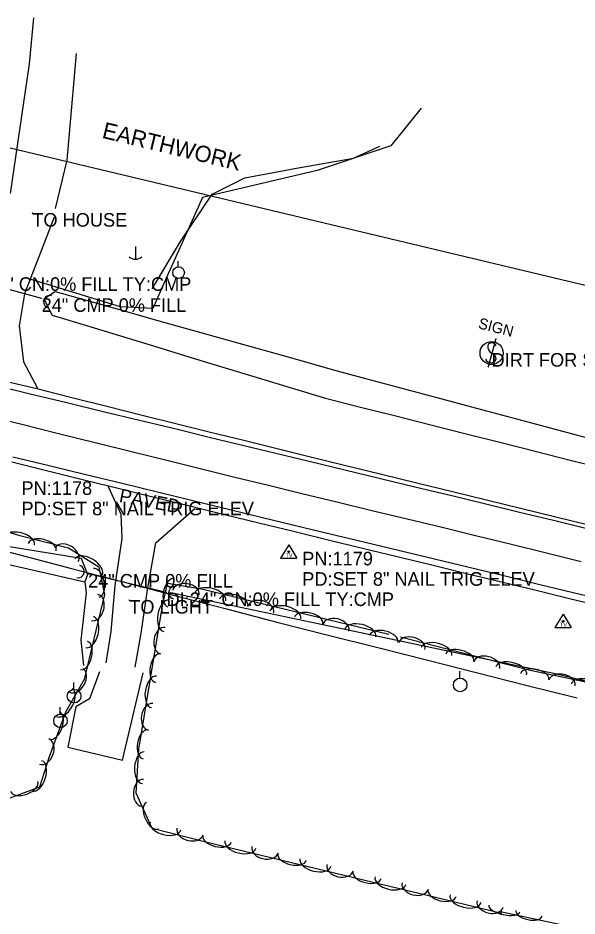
# Model space of a CAD drawing. Extents: x 1441650 to 1491889, y 345904 to 358319.
# Drawn here: x 1458522.3 to 1458728.2, y 351345.2 to 351675.9 of the extents above; entities that cross this region are included whole.
import ezdxf

# ---------------------------------------------------------------- set-up
doc = ezdxf.new("R2010")
doc.units = 0
for name, color, linetype in [('S_CROSS_DRAIN', 7, 'Continuous'), ('S_CROSS_DRAIN_ANNOT', 7, 'Continuous'), ('S_DITCHLINE', 7, 'Continuous'), ('S_DRG_PT_SYM', 7, 'Continuous'), ('S_EDGE_PAVEMENT', 7, 'Continuous'), ('S_GRAVEL_ROAD', 7, 'Continuous'), ('S_MISC_BOUNDARY', 7, 'Continuous'), ('S_MISC_BOUNDARY_ANNOT', 7, 'Continuous'), ('S_MSC_PT_SYM', 7, 'Continuous'), ('S_PARKING', 7, 'Continuous'), ('S_PARKING_ANNOT', 7, 'Continuous'), ('S_PAVEMENT_CROWN', 7, 'Continuous'), ('S_SECONDARY_CTL', 7, 'Continuous'), ('S_SECONDARY_CTL_ANNOT', 7, 'Continuous'), ('S_SHOULDER', 7, 'Continuous'), ('S_SIGN', 7, 'Continuous'), ('S_SIGN_ANNOT', 7, 'Continuous'), ('S_STREAM', 7, 'Continuous'), ('S_SURVEY_TEXT_ANNOT', 7, 'Continuous'), ('S_TREE', 7, 'Continuous'), ('S_UTILITY_POLE', 7, 'Continuous'), ('S_WATER_UTILITIES', 7, 'Continuous')]:
    doc.layers.add(name, color=color, linetype=linetype)

msp = doc.modelspace()

# ---------------------------------------------------------------- linework, layer by layer
at = {"layer": 'S_CROSS_DRAIN'}
for p, q in [((1458502.43, 351580.4), (1458531.05, 351572.66)), ((1458577.05, 351464.33), (1458548.17, 351471.12))]:
    msp.add_line(p, q, dxfattribs=at)
for centre, start, end in [((1458534.06, 351571.39), 74.1339, 254.463), ((1458544.46, 351472.05), 257.4017, 77.7308), ((1458580.1, 351464.22), 76.0714, 256.4006)]:
    msp.add_arc(centre, 2.3, start, end, dxfattribs=at)
at = {"layer": 'S_DITCHLINE'}
for points in [[(1458531.81, 351572.44), (1458536.01, 351575.16), (1458548.76, 351571.58), (1458561.51, 351568), (1458574.26, 351564.41), (1458587.01, 351560.83), (1458599.76, 351557.24), (1458612.51, 351553.66), (1458625.26, 351550.08), (1458638.01, 351546.49), (1458650.86, 351543.05), (1458663.7, 351539.6), (1458676.55, 351536.16), (1458689.39, 351532.71), (1458702.24, 351529.27), (1458715.09, 351525.82), (1458727.93, 351522.38), (1458740.78, 351518.93), (1458764.46, 351513.29), (1458788.14, 351507.66), (1458811.82, 351502.02), (1458835.51, 351496.38)], [(1458531.82, 351572.47), (1458531.81, 351572.44), (1458534.96, 351566.41), (1458547.53, 351562.59), (1458560.1, 351558.78), (1458572.67, 351554.97), (1458585.24, 351551.15), (1458597.81, 351547.34), (1458610.39, 351543.52), (1458622.96, 351539.71), (1458635.53, 351535.9), (1458648.48, 351532.62), (1458661.44, 351529.35), (1458674.4, 351526.07), (1458687.35, 351522.8), (1458700.31, 351519.53), (1458713.27, 351516.25), (1458726.22, 351512.98), (1458739.18, 351509.7)], [(1458512.39, 351482.35), (1458528.99, 351479.68), (1458545.6, 351477.01), (1458548, 351470.96), (1458547, 351468.22), (1458547.4, 351464.15), (1458545.54, 351446.8), (1458546.42, 351437.38)], [(1458510.32, 351476.59), (1458528.66, 351472.41), (1458547, 351468.23)]]:
    msp.add_lwpolyline(points, dxfattribs=at)
at = {"layer": 'S_DRG_PT_SYM'}
for points in [[(1458531.05, 351572.66), (1458531.05, 351572.71), (1458531.05, 351572.66), (1458531, 351572.66), (1458531.05, 351572.66), (1458531.05, 351572.61), (1458531.05, 351572.66), (1458531.1, 351572.66)], [(1458548.17, 351471.12), (1458548.17, 351471.17), (1458548.17, 351471.12), (1458548.12, 351471.12), (1458548.17, 351471.12), (1458548.17, 351471.07), (1458548.17, 351471.12), (1458548.22, 351471.12)], [(1458577.05, 351464.33), (1458577.05, 351464.38), (1458577.05, 351464.33), (1458577, 351464.33), (1458577.05, 351464.33), (1458577.05, 351464.28), (1458577.05, 351464.33), (1458577.1, 351464.33)]]:
    msp.add_lwpolyline(points, dxfattribs=at)
at = {"layer": 'S_EDGE_PAVEMENT'}
for points in [[(1458514.28, 351540.54), (1458526.88, 351537.49), (1458540.3, 351534.25), (1458553.73, 351531.01), (1458567.15, 351527.77), (1458580.58, 351524.53), (1458592.81, 351521.56), (1458605.05, 351518.6), (1458617.28, 351515.64), (1458629.52, 351512.68), (1458642.68, 351509.5), (1458655.84, 351506.32), (1458668.99, 351503.15), (1458682.15, 351499.97), (1458694.61, 351496.95), (1458707.07, 351493.93), (1458719.53, 351490.91), (1458731.98, 351487.89)], [(1458520.44, 351514.32), (1458533.87, 351511.06), (1458547.3, 351507.79), (1458560.73, 351504.53), (1458574.16, 351501.26), (1458586.76, 351498.2), (1458599.36, 351495.13), (1458611.96, 351492.07), (1458624.56, 351489), (1458637.35, 351485.92), (1458650.14, 351482.85), (1458662.93, 351479.77), (1458675.72, 351476.69), (1458688.5, 351473.6), (1458701.27, 351470.51), (1458714.05, 351467.42), (1458726.82, 351464.33), (1458739.73, 351461.21)]]:
    msp.add_lwpolyline(points, dxfattribs=at)
at = {"layer": 'S_GRAVEL_ROAD'}
for points in [[(1458535.7, 351602.49), (1458530.04, 351587.89), (1458524.73, 351574.32), (1458522.76, 351562.46), (1458524.36, 351549.28), (1458529.55, 351539.62)], [(1458555.6, 351503.3), (1458560.22, 351493.14), (1458560.61, 351484.24), (1458557.96, 351466.92), (1458556.49, 351449.97), (1458554.67, 351438.38)], [(1458565.52, 351436.8), (1458567.75, 351449.37), (1458570.01, 351465.31), (1458573.15, 351482.64), (1458587.47, 351495.24), (1458587.55, 351495.23)]]:
    msp.add_lwpolyline(points, dxfattribs=at)
at = {"layer": 'S_MISC_BOUNDARY'}
msp.add_lwpolyline([(1458670.83, 351642.69), (1458659.69, 351628.83), (1458632.47, 351619.67), (1458590.27, 351609.76), (1458576.07, 351578.08), (1458571.97, 351568.89), (1458560.12, 351569.49), (1458527.15, 351579.6)], dxfattribs=at)
at = {"layer": 'S_MSC_PT_SYM'}
for points in [[(1458527.64, 351604.04), (1458527.64, 351604.09), (1458527.64, 351604.04), (1458527.59, 351604.04), (1458527.64, 351604.04), (1458527.64, 351603.99), (1458527.64, 351604.04), (1458527.69, 351604.04)], [(1458698.33, 351557.73), (1458698.33, 351557.78), (1458698.33, 351557.73), (1458698.28, 351557.73), (1458698.33, 351557.73), (1458698.33, 351557.68), (1458698.33, 351557.73), (1458698.38, 351557.73)], [(1458695.54, 351547.46), (1458695.54, 351547.51), (1458695.54, 351547.46), (1458695.49, 351547.46), (1458695.54, 351547.46), (1458695.54, 351547.41), (1458695.54, 351547.46), (1458695.59, 351547.46)], [(1458563.32, 351461.54), (1458563.32, 351461.59), (1458563.32, 351461.54), (1458563.27, 351461.54), (1458563.32, 351461.54), (1458563.32, 351461.49), (1458563.32, 351461.54), (1458563.37, 351461.54)]]:
    msp.add_lwpolyline(points, dxfattribs=at)
at = {"layer": 'S_PARKING'}
for points in [[(1458519.58, 351611.25), (1458526.63, 351658.97), (1458528.14, 351675.9)], [(1458543.81, 351662.77), (1458540.38, 351623.51), (1458536.1, 351605.74)], [(1458552.34, 351435.08), (1458548.67, 351425.12), (1458543.65, 351422.15), (1458540.71, 351407.39), (1458560.8, 351402.55), (1458568.47, 351434.67)]]:
    msp.add_lwpolyline(points, dxfattribs=at)
at = {"layer": 'S_PAVEMENT_CROWN'}
msp.add_lwpolyline([(1458511.34, 351529.24), (1458523.77, 351526.24), (1458537.24, 351522.9), (1458550.71, 351519.55), (1458564.18, 351516.21), (1458577.65, 351512.87), (1458589.95, 351509.84), (1458602.26, 351506.82), (1458614.56, 351503.8), (1458626.87, 351500.78), (1458639.79, 351497.67), (1458652.71, 351494.55), (1458665.63, 351491.44), (1458678.55, 351488.33), (1458691.35, 351485.19), (1458704.14, 351482.05), (1458716.94, 351478.9), (1458729.73, 351475.76)], dxfattribs=at)
at = {"layer": 'S_SECONDARY_CTL'}
for p, q in [((1458622.03, 351481.92), (1458619.02, 351476.96)), ((1458622.03, 351481.92), (1458624.98, 351476.96)), ((1458619.02, 351476.96), (1458624.98, 351476.96)), ((1458723.11, 351456.33), (1458720.1, 351451.38)), ((1458723.11, 351456.33), (1458726.05, 351451.38)), ((1458720.1, 351451.38), (1458726.05, 351451.38))]:
    msp.add_line(p, q, dxfattribs=at)
for centre, radius in [((1458622.03, 351479.3), 0.311), ((1458622.03, 351479.3), 0.183), ((1458622.03, 351479.3), 0.103), ((1458723.11, 351453.72), 0.311), ((1458723.11, 351453.72), 0.183), ((1458723.11, 351453.72), 0.103)]:
    msp.add_circle(centre, radius, dxfattribs=at)
at = {"layer": 'S_SHOULDER'}
for points in [[(1458516.19, 351542.5), (1458529.3, 351539.43), (1458542.21, 351536.17), (1458555.12, 351532.9), (1458568.03, 351529.64), (1458580.94, 351526.38), (1458593.21, 351523.37), (1458605.48, 351520.35), (1458617.75, 351517.34), (1458630.02, 351514.32), (1458643.11, 351511.11), (1458656.2, 351507.89), (1458669.28, 351504.67), (1458682.37, 351501.45), (1458694.87, 351498.41), (1458707.38, 351495.37), (1458719.88, 351492.33), (1458732.38, 351489.28)], [(1458520.14, 351512.4), (1458533.34, 351509.12), (1458546.54, 351505.84), (1458559.75, 351502.56), (1458572.95, 351499.28), (1458585.66, 351496.18), (1458598.37, 351493.08), (1458611.08, 351489.98), (1458623.79, 351486.87), (1458636.53, 351483.76), (1458649.27, 351480.66), (1458662.01, 351477.55), (1458674.75, 351474.44), (1458687.55, 351471.33), (1458700.34, 351468.22), (1458713.13, 351465.11), (1458725.93, 351462), (1458738.93, 351458.88)]]:
    msp.add_lwpolyline(points, dxfattribs=at)
at = {"layer": 'S_SIGN'}
msp.add_line((1458698.33, 351557.73), (1458695.54, 351547.46), dxfattribs=at)
msp.add_circle((1458696.74, 351552.49), 4.24, dxfattribs=at)
for centre, radius, start, end in [((1458696.87, 351554.65), 1.62, 16.5258, 156.8957), ((1458697.91, 351554.74), 2.55, 167.1196, 241.9813), ((1458696.48, 351551.09), 2.17, 204.641, 335.359), ((1458696.04, 351550.21), 2.38, 358.6529, 73.7063)]:
    msp.add_arc(centre, radius, start, end, dxfattribs=at)
at = {"layer": 'S_STREAM'}
for points in [[(1458571.71, 351576.18), (1458582.17, 351593.54), (1458593.85, 351610.96), (1458605.89, 351616.99), (1458624.95, 351620.63), (1458645.84, 351624.26), (1458655.54, 351628.67)], [(1458578.61, 351464.35), (1458632.28, 351453), (1458720.19, 351434.47), (1458817.6, 351411.03), (1458920.11, 351387.75), (1459007.82, 351366.75), (1459084.49, 351347.81), (1459170.91, 351328.16), (1459288.39, 351301.52), (1459381.79, 351277.55), (1459486.81, 351250.35), (1459558.24, 351231.73), (1459664.82, 351202.09)]]:
    msp.add_lwpolyline(points, dxfattribs=at)
at = {"layer": 'S_TREE'}
for points in [[(1458482.5, 351497.64), (1458523.05, 351485.26), (1458540.91, 351480.75), (1458552.18, 351473.8), (1458554.24, 351463.57), (1458550.3, 351447.24), (1458546.7, 351432.31), (1458539.83, 351420.23), (1458533.72, 351403.42), (1458530.21, 351392.58), (1458517.97, 351388.12), (1458470.23, 351399.5), (1458352.75, 351427.72), (1458253.25, 351451.71), (1458168.6, 351472.11), (1458080.78, 351493.28), (1457975, 351518.81)], [(1458504.02, 351483.11), (1458523.05, 351478.13), (1458542.09, 351473.16), (1458561.12, 351468.19), (1458580.15, 351463.21), (1458599.18, 351458.24), (1458618.21, 351453.27), (1458636.54, 351448.63), (1458654.88, 351444), (1458673.22, 351439.37), (1458691.56, 351434.73), (1458709.9, 351430.1), (1458728.23, 351425.46)], [(1458504.02, 351483.11), (1458523.05, 351478.13), (1458542.09, 351473.16), (1458561.12, 351468.19), (1458580.15, 351463.21), (1458599.18, 351458.24), (1458618.21, 351453.27), (1458636.54, 351448.63), (1458654.88, 351444), (1458673.22, 351439.37), (1458691.56, 351434.73), (1458709.9, 351430.1), (1458728.23, 351425.46)], [(1458700.49, 351346.14), (1458591.52, 351372.4), (1458571.7, 351377.34), (1458565.84, 351390.42), (1458566.8, 351406.55), (1458575.51, 351459.45), (1458577.42, 351467.73), (1458589.88, 351465.64), (1458632.47, 351455.37), (1458658.95, 351448.99)], [(1458663.18, 351448.03), (1458711.01, 351435.73), (1458759.57, 351425.5), (1458796.96, 351415.82), (1458856.35, 351399.3), (1458956.09, 351373.48), (1459049.81, 351352.01), (1459148.97, 351326.34), (1459247.8, 351301.46), (1459338.76, 351279.57), (1459440.78, 351257.04), (1459527.02, 351234.71), (1459625.47, 351213.15), (1459671.91, 351201.13), (1459683.42, 351198.15)], [(1459653.76, 351114.56), (1459499.42, 351153.65), (1459384.1, 351181.62), (1459274.65, 351206.88), (1459222.5, 351219.2), (1459116.91, 351246.53), (1459028.16, 351266.78), (1458976.84, 351280.06), (1458875.39, 351301.41), (1458841.5, 351311.25), (1458791.59, 351327.01), (1458699.46, 351346.83)]]:
    msp.add_lwpolyline(points, dxfattribs=at)
for centre, major_axis, ratio, start_param, end_param in [((1458522.76, 351483.14), (-5.62, 1.43), 0.55612, 3.145692, 6.287285), ((1458531.26, 351481), (-5.12, 1.31), 0.546637, 3.145562, 6.287155), ((1458540.31, 351478.32), (-4.2, 2.6), 0.686629, 3.14437, 6.285963), ((1458548.31, 351473.69), (-4.98, 3.07), 0.551139, 3.143285, 6.284878), ((1458551.21, 351467.87), (-1.06, 5.24), 0.540694, 3.141504, 6.283096), ((1458578.8, 351464.29), (-1.21, -5.21), 0.540699, 3.141593, 6.283185), ((1458584.19, 351464.18), (-4.89, 0.82), 0.685311, 3.141593, 6.283185), ((1458550.63, 351458.8), (1.16, 4.82), 0.685315, 3.141574, 6.283167), ((1458593.16, 351462.66), (-5.7, 1.38), 0.55008, 3.141593, 6.283185), ((1458601.78, 351460.59), (-5.2, 1.25), 0.540699, 3.141593, 6.283185), ((1458577.05, 351455.74), (-0.95, -5.79), 0.55008, 3.141593, 6.283185), ((1458611.74, 351457.92), (-4.82, 1.16), 0.685311, 3.141593, 6.283185), ((1458620.8, 351456), (-5.7, 1.38), 0.55008, 3.141593, 6.283185), ((1458629.42, 351453.92), (-5.2, 1.25), 0.540699, 3.141593, 6.283185), ((1458548.72, 351449.73), (1.38, 5.7), 0.550083, 3.141581, 6.283174), ((1458639.37, 351451.26), (-4.82, 1.16), 0.685311, 3.141593, 6.283185), ((1458575.8, 351446.57), (-0.8, -4.89), 0.685311, 3.141593, 6.283185), ((1458648.43, 351449.34), (-5.7, 1.38), 0.55008, 3.141593, 6.283185), ((1458657.05, 351447.26), (-5.2, 1.25), 0.540699, 3.141593, 6.283185), ((1458667.41, 351444.59), (-4.8, 1.23), 0.654284, 3.141593, 6.283185), ((1458546.64, 351441.11), (1.25, 5.2), 0.540697, 3.141593, 6.283185), ((1458676.44, 351442.53), (-5.68, 1.46), 0.525175, 3.141593, 6.283185), ((1458685.03, 351440.32), (-5.18, 1.33), 0.51622, 3.141593, 6.283185), ((1458573.87, 351436.44), (-0.87, -5.28), 0.540699, 3.141593, 6.283185), ((1458694.94, 351437.51), (-4.8, 1.23), 0.654284, 3.141593, 6.283185), ((1458703.97, 351435.44), (-5.68, 1.46), 0.525175, 3.141593, 6.283185), ((1458543.76, 351431.96), (2.45, 4.31), 0.685262, 3.141549, 6.283141), ((1458572.43, 351427.69), (-0.95, -5.79), 0.55008, 3.141593, 6.283185), ((1458712.66, 351433.31), (-5.23, 1.1), 0.51625, 3.140604, 6.282197), ((1458722.69, 351430.94), (-4.85, 1.02), 0.654322, 3.139985, 6.281578), ((1458731.8, 351429.28), (-5.74, 1.21), 0.525207, 3.140574, 6.282166), ((1458539.41, 351423.78), (2.9, 5.1), 0.550041, 3.141566, 6.283159), ((1458571.19, 351418.52), (-0.8, -4.89), 0.685311, 3.141593, 6.283185), ((1458535.79, 351415.33), (1.83, 5.02), 0.540687, 3.141593, 6.283185), ((1458569.26, 351408.39), (-0.87, -5.28), 0.540699, 3.141593, 6.283185), ((1458532.02, 351405.74), (1.69, 4.66), 0.685295, 3.141593, 6.283185), ((1458568.52, 351399.78), (-0.35, -5.86), 0.55008, 3.141593, 6.283185), ((1458529.34, 351396.78), (1.8, 5.58), 0.550071, 3.141593, 6.283185), ((1458524.66, 351392.81), (5.02, 1.83), 0.540463, 3.141593, 6.283185), ((1458568.23, 351390.53), (-0.3, -4.95), 0.685311, 3.141593, 6.283185), ((1458571.89, 351382.12), (2.19, -4.88), 0.540699, 3.141593, 6.283185), ((1458576.66, 351378.29), (5.69, -1.42), 0.55008, 3.141593, 6.283185), ((1458585.71, 351376.3), (4.81, -1.2), 0.685311, 3.141593, 6.283185), ((1458595.64, 351373.59), (5.2, -1.25), 0.540699, 3.141593, 6.283185), ((1458604.26, 351371.51), (5.7, -1.38), 0.55008, 3.141593, 6.283185), ((1458613.32, 351369.6), (4.82, -1.16), 0.685311, 3.141593, 6.283185), ((1458623.27, 351366.93), (5.2, -1.25), 0.540699, 3.141593, 6.283185), ((1458631.89, 351364.85), (5.7, -1.38), 0.55008, 3.141593, 6.283185), ((1458640.95, 351362.94), (4.82, -1.16), 0.685311, 3.141593, 6.283185), ((1458650.91, 351360.27), (5.2, -1.25), 0.540699, 3.141593, 6.283185), ((1458659.53, 351358.19), (5.7, -1.38), 0.55008, 3.141593, 6.283185), ((1458668.59, 351356.27), (4.82, -1.16), 0.685311, 3.141593, 6.283185), ((1458678.54, 351353.61), (5.2, -1.25), 0.540699, 3.141593, 6.283185), ((1458687.17, 351351.53), (5.7, -1.38), 0.55008, 3.141593, 6.283185), ((1458696.23, 351349.61), (4.82, -1.16), 0.685311, 3.141593, 6.283185), ((1458701.42, 351347.93), (5.73, -1.26), 0.387863, 3.154269, 6.295862), ((1458710.5, 351346.17), (4.83, -1.08), 0.483168, 3.159096, 6.300688)]:
    msp.add_ellipse(centre, major_axis=major_axis, ratio=ratio, start_param=start_param, end_param=end_param, dxfattribs=at)
at = {"layer": 'S_UTILITY_POLE'}
for p, q in [((1458565.58, 351591.73), (1458565.58, 351587.01)), ((1458581.39, 351584.24), (1458581.39, 351586.35)), ((1458685.04, 351432.8), (1458685.04, 351435.28)), ((1458542.87, 351428.65), (1458542.87, 351431.13)), ((1458537.84, 351419.57), (1458537.84, 351422.05))]:
    msp.add_line(p, q, dxfattribs=at)
for centre, radius in [((1458581.51, 351582.1), 2.13), ((1458685.18, 351430.28), 2.5), ((1458543.02, 351426.13), 2.5), ((1458537.99, 351417.05), 2.5)]:
    msp.add_circle(centre, radius, dxfattribs=at)
msp.add_arc((1458565.64, 351590.43), 3.41, 226.3972, 313.6028, dxfattribs=at)
at = {"layer": 'S_WATER_UTILITIES'}
msp.add_line((1458511.04, 351630.06), (1458843.16, 351550.73), dxfattribs=at)

# ---------------------------------------------------------------- texts
at = {"layer": 'S_CROSS_DRAIN_ANNOT'}
for s, p in [('DI:24" CN:0% FILL TY:CMP', (1458502.43, 351575.4)), ('24" CMP 0% FILL', (1458531.05, 351567.66)), ('24" CMP 0% FILL', (1458548.17, 351466.12)), ('DI:24" CN:0% FILL TY:CMP', (1458577.05, 351459.33))]:
    msp.add_text(s, height=5, dxfattribs=at).set_placement(p)
at = {"layer": 'S_MISC_BOUNDARY_ANNOT'}
msp.add_text('EARTHWORK', height=6, rotation=346.4469, dxfattribs=at).set_placement((1458553, 351631.8))
at = {"layer": 'S_PARKING_ANNOT'}
msp.add_text('PAVED', height=5, rotation=349.0406, dxfattribs=at).set_placement((1458559.35, 351497.68))
at = {"layer": 'S_SECONDARY_CTL'}
for p in [(1458620.83, 351477.29), (1458721.9, 351451.71)]:
    msp.add_text('TV', height=1.5, rotation=360, dxfattribs=at).set_placement(p)
at = {"layer": 'S_SECONDARY_CTL_ANNOT'}
for s, p in [('PN:1178', (1458523.63, 351500.24)), ('PD:SET 8" NAIL TRIG ELEV', (1458523.63, 351492.74)), ('PN:1179', (1458627.03, 351474.3)), ('PD:SET 8" NAIL TRIG ELEV', (1458627.03, 351466.8))]:
    msp.add_text(s, height=5, dxfattribs=at).set_placement(p)
at = {"layer": 'S_SIGN_ANNOT'}
msp.add_text('SIGN', height=4, rotation=345.4868, dxfattribs=at).set_placement((1458691.57, 351561.69))
msp.add_text('DIRT FOR SALE', height=5, dxfattribs=at).set_placement((1458696.74, 351547.49))
at = {"layer": 'S_SURVEY_TEXT_ANNOT'}
for s, p in [('TO HOUSE', (1458527.64, 351599.04)), ('TO LIGHT', (1458563.32, 351456.54))]:
    msp.add_text(s, height=5, dxfattribs=at).set_placement(p)

doc.saveas('drawing.dxf')
